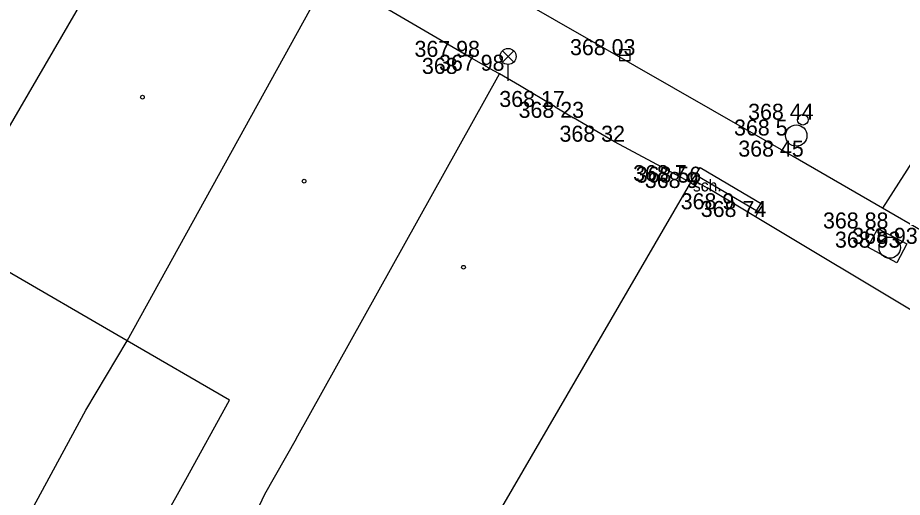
# Model space of a CAD drawing. Extents: x -688316 to -688024, y -973785 to -973591.
# Drawn here: x -688150.19 to -688108.72, y -973719.16 to -973696.66 of the extents above; entities that cross this region are included whole.
import ezdxf

# ---------------------------------------------------------------- set-up
doc = ezdxf.new("R2010")
doc.units = 0
for name, color, linetype in [('Vrstva 10', 7, 'Continuous'), ('Vrstva 11', 7, 'Continuous'), ('Vrstva 27', 7, 'Continuous'), ('Vrstva 28_Verejne osvetleni', 7, 'Continuous'), ('Vrstva 3', 7, 'Continuous'), ('Vrstva 33', 7, 'Continuous'), ('Vrstva 41', 7, 'Continuous'), ('Vrstva 5', 7, 'Continuous'), ('Vrstva 56', 7, 'Continuous'), ('Vrstva 58', 7, 'Continuous'), ('Vrstva 6', 7, 'Continuous'), ('Vrstva 7', 7, 'Continuous')]:
    doc.layers.add(name, color=color, linetype=linetype)

# ---------------------------------------------------------------- blocks, each defined once
blk = doc.blocks.new('B_NESP')
at = {"layer": 'Vrstva 58'}
blk.add_circle((0, 0), 0.875, dxfattribs=at)
blk = doc.blocks.new('SKSCH0')
at = {"layer": 'Vrstva 41'}
blk.add_text('sch.', height=5.5, dxfattribs=at).set_placement((-8.15, -3.04))
blk = doc.blocks.new('VP')
at = {"layer": 'Vrstva 27'}
blk.add_line((-2.5, 0), (2.5, 0), dxfattribs=at)
blk.add_lwpolyline([(-2.5, -2.5), (2.5, -2.5), (2.5, 2.5), (-2.5, 2.5)], close=True, dxfattribs=at)
blk = doc.blocks.new('SAK')
at = {"layer": 'Vrstva 27'}
blk.add_circle((0, 0), 5, dxfattribs=at)
blk = doc.blocks.new('SV')
at = {"layer": 'Vrstva 28_Verejne osvetleni'}
blk.add_circle((0, 0), 2.5, dxfattribs=at)
blk = doc.blocks.new('LAO')
at = {"layer": 'Vrstva 33'}
for p, q in [((-2.65, 14.16), (2.65, 8.85)), ((-2.65, 8.85), (2.65, 14.16)), ((0, 0), (0, 7.75))]:
    blk.add_line(p, q, dxfattribs=at)
blk.add_circle((0, 11.5), 3.75, dxfattribs=at)

msp = doc.modelspace()

# ---------------------------------------------------------------- linework, layer by layer
at = {"layer": 'Vrstva 10'}
for p, q in [((-688113.84, -973703.18), (-688128.61, -973694.7)), ((-688104.76, -973697.92), (-688109.65, -973705.6)), ((-688109.65, -973705.6), (-688113.84, -973703.18)), ((-688098.57, -973712.02), (-688109.65, -973705.6))]:
    msp.add_line(p, q, dxfattribs=at)
msp.add_lwpolyline([(-688109.87, -973706.55), (-688108.5, -973707.27), (-688108.98, -973708.16), (-688110.34, -973707.43), (-688109.87, -973706.55)], dxfattribs=at)
at = {"layer": 'Vrstva 11'}
msp.add_lwpolyline([(-688118.65, -973704.4), (-688118.4, -973704.04), (-688118.19, -973703.69), (-688115.26, -973705.42), (-688115.47, -973705.76), (-688115.6, -973706.01)], dxfattribs=at)
at = {"layer": 'Vrstva 5'}
for p, q in [((-688153.55, -973706.89), (-688143.74, -973689.99)), ((-688145.05, -973711.82), (-688135.58, -973694.66)), ((-688137.14, -973716.41), (-688127.6, -973699.3)), ((-688124.99, -973700.85), (-688124.14, -973701.36)), ((-688118.65, -973704.4), (-688122.21, -973702.48)), ((-688118.65, -973704.4), (-688129.85, -973723.67)), ((-688115.6, -973706.01), (-688116.19, -973705.65)), ((-688101.32, -973714.57), (-688115.6, -973706.01)), ((-688145.05, -973711.82), (-688153.55, -973706.89)), ((-688140.26, -973714.6), (-688145.05, -973711.82)), ((-688142.31, -973718.32), (-688140.26, -973714.6)), ((-688137.14, -973716.41), (-688138.61, -973719.03)), ((-688146.85, -973726.56), (-688142.31, -973718.32)), ((-688138.61, -973719.03), (-688143.36, -973728.87))]:
    msp.add_line(p, q, dxfattribs=at)
for points in [[(-688129.02, -973698.5), (-688135.58, -973694.66), (-688142.07, -973691)], [(-688126.67, -973699.85), (-688127.6, -973699.3), (-688127.87, -973699.15)], [(-688118.65, -973704.4), (-688118.51, -973704.48), (-688118.42, -973704.33), (-688117.87, -973704.65)]]:
    msp.add_lwpolyline(points, dxfattribs=at)
at = {"layer": 'Vrstva 56'}
msp.add_line((-688118.4, -973704.04), (-688115.47, -973705.76), dxfattribs=at)
at = {"layer": 'Vrstva 6'}
for p, q in [((-688127.87, -973699.15), (-688129.02, -973698.5)), ((-688124.99, -973700.85), (-688126.67, -973699.85)), ((-688122.21, -973702.48), (-688124.14, -973701.36)), ((-688116.19, -973705.65), (-688117.87, -973704.65))]:
    msp.add_line(p, q, dxfattribs=at)
at = {"layer": 'Vrstva 7'}
for p, q in [((-688147, -973715.07), (-688145.05, -973711.82)), ((-688151.48, -973723.34), (-688147, -973715.07))]:
    msp.add_line(p, q, dxfattribs=at)

# ---------------------------------------------------------------- block references
at = {"layer": 'Vrstva 27', "xscale": 0.1, "yscale": 0.10000000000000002}
for name, p in [('VP', (-688121.73, -973698.42)), ('SAK', (-688113.69, -973702.19)), ('SAK', (-688109.31, -973707.45))]:
    msp.add_blockref(name, p, dxfattribs=at)
at = {"layer": 'Vrstva 28_Verejne osvetleni', "xscale": 0.1, "yscale": 0.10000000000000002}
msp.add_blockref('SV', (-688113.38, -973701.45), dxfattribs=at)
at = {"layer": 'Vrstva 33', "xscale": 0.1, "yscale": 0.10000000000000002}
msp.add_blockref('LAO', (-688127.2, -973699.63), dxfattribs=at)
at = {"layer": 'Vrstva 41', "xscale": 0.1, "yscale": 0.10000000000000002}
msp.add_blockref('SKSCH0', (-688117.72, -973704.51), dxfattribs=at)
at = {"layer": 'Vrstva 58', "xscale": 0.1, "yscale": 0.10000000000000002}
for p in [(-688144.34, -973700.39), (-688144.34, -973700.39), (-688144.34, -973700.39), (-688144.34, -973700.39), (-688136.76, -973704.33), (-688136.76, -973704.33), (-688136.76, -973704.33), (-688136.76, -973704.33), (-688129.29, -973708.37), (-688129.29, -973708.37), (-688129.29, -973708.37), (-688129.29, -973708.37)]:
    msp.add_blockref('B_NESP', p, dxfattribs=at)

# ---------------------------------------------------------------- texts
at = {"layer": 'Vrstva 3'}
for s, p in [('367 98 ', (-688131.586, -973698.5)), ('367 98 ', (-688131.586, -973698.5)), ('367 98 ', (-688131.586, -973698.5)), ('367 98 ', (-688131.586, -973698.5)), ('367 98 ', (-688131.586, -973698.5)), ('367 98 ', (-688131.586, -973698.5)), ('367 98 ', (-688131.586, -973698.5)), ('368 03 ', (-688124.296, -973698.42)), ('368 03 ', (-688124.296, -973698.42)), ('368 03 ', (-688124.296, -973698.42)), ('368 03 ', (-688124.296, -973698.42)), ('368 03 ', (-688124.296, -973698.42)), ('368 03 ', (-688124.296, -973698.42)), ('368 03 ', (-688124.296, -973698.42)), ('367 98 ', (-688130.436, -973699.15)), ('367 98 ', (-688130.436, -973699.15)), ('367 98 ', (-688130.436, -973699.15)), ('367 98 ', (-688130.436, -973699.15)), ('367 98 ', (-688130.436, -973699.15)), ('367 98 ', (-688130.436, -973699.15)), ('367 98 ', (-688130.436, -973699.15)), ('368    ', (-688131.237, -973699.3)), ('368    ', (-688131.237, -973699.3)), ('368    ', (-688131.237, -973699.3)), ('368    ', (-688131.237, -973699.3)), ('368    ', (-688131.237, -973699.3)), ('368    ', (-688131.237, -973699.3)), ('368    ', (-688131.237, -973699.3)), ('368 17 ', (-688127.611, -973700.85)), ('368 17 ', (-688127.611, -973700.85)), ('368 17 ', (-688127.611, -973700.85)), ('368 17 ', (-688127.611, -973700.85)), ('368 17 ', (-688127.611, -973700.85)), ('368 17 ', (-688127.611, -973700.85)), ('368 17 ', (-688127.611, -973700.85)), ('368 23 ', (-688126.706, -973701.36)), ('368 23 ', (-688126.706, -973701.36)), ('368 23 ', (-688126.706, -973701.36)), ('368 23 ', (-688126.706, -973701.36)), ('368 23 ', (-688126.706, -973701.36)), ('368 23 ', (-688126.706, -973701.36)), ('368 23 ', (-688126.706, -973701.36)), ('368 44 ', (-688115.946, -973701.45)), ('368 44 ', (-688115.946, -973701.45)), ('368 44 ', (-688115.946, -973701.45)), ('368 44 ', (-688115.946, -973701.45)), ('368 44 ', (-688115.946, -973701.45)), ('368 44 ', (-688115.946, -973701.45)), ('368 44 ', (-688115.946, -973701.45)), ('368 5  ', (-688116.607, -973702.19)), ('368 5  ', (-688116.607, -973702.19)), ('368 5  ', (-688116.607, -973702.19)), ('368 5  ', (-688116.607, -973702.19)), ('368 5  ', (-688116.607, -973702.19)), ('368 5  ', (-688116.607, -973702.19)), ('368 5  ', (-688116.607, -973702.19)), ('368 32 ', (-688124.788, -973702.48)), ('368 32 ', (-688124.788, -973702.48)), ('368 32 ', (-688124.788, -973702.48)), ('368 32 ', (-688124.788, -973702.48)), ('368 32 ', (-688124.788, -973702.48)), ('368 32 ', (-688124.788, -973702.48)), ('368 32 ', (-688124.788, -973702.48)), ('368 45 ', (-688116.406, -973703.18)), ('368 45 ', (-688116.406, -973703.18)), ('368 45 ', (-688116.406, -973703.18)), ('368 45 ', (-688116.406, -973703.18)), ('368 45 ', (-688116.406, -973703.18)), ('368 45 ', (-688116.406, -973703.18)), ('368 45 ', (-688116.406, -973703.18)), ('368 7  ', (-688121.337, -973704.33)), ('368 7  ', (-688121.337, -973704.33)), ('368 7  ', (-688121.337, -973704.33)), ('368 7  ', (-688121.337, -973704.33)), ('368 7  ', (-688121.337, -973704.33)), ('368 7  ', (-688121.337, -973704.33)), ('368 7  ', (-688121.337, -973704.33)), ('368 56 ', (-688121.216, -973704.4)), ('368 56 ', (-688121.216, -973704.4)), ('368 56 ', (-688121.216, -973704.4)), ('368 56 ', (-688121.216, -973704.4)), ('368 56 ', (-688121.216, -973704.4)), ('368 56 ', (-688121.216, -973704.4)), ('368 56 ', (-688121.216, -973704.4)), ('368 9  ', (-688120.787, -973704.65)), ('368 9  ', (-688120.787, -973704.65)), ('368 9  ', (-688120.787, -973704.65)), ('368 9  ', (-688120.787, -973704.65)), ('368 9  ', (-688120.787, -973704.65)), ('368 9  ', (-688120.787, -973704.65)), ('368 9  ', (-688120.787, -973704.65)), ('368 9  ', (-688119.107, -973705.65)), ('368 9  ', (-688119.107, -973705.65)), ('368 9  ', (-688119.107, -973705.65)), ('368 9  ', (-688119.107, -973705.65)), ('368 9  ', (-688119.107, -973705.65)), ('368 9  ', (-688119.107, -973705.65)), ('368 9  ', (-688119.107, -973705.65)), ('368 74 ', (-688118.166, -973706.01)), ('368 74 ', (-688118.166, -973706.01)), ('368 74 ', (-688118.166, -973706.01)), ('368 74 ', (-688118.166, -973706.01)), ('368 74 ', (-688118.166, -973706.01)), ('368 74 ', (-688118.166, -973706.01)), ('368 74 ', (-688118.166, -973706.01)), ('368 88 ', (-688112.436, -973706.55)), ('368 88 ', (-688112.436, -973706.55)), ('368 88 ', (-688112.436, -973706.55)), ('368 88 ', (-688112.436, -973706.55)), ('368 88 ', (-688112.436, -973706.55)), ('368 88 ', (-688112.436, -973706.55)), ('368 88 ', (-688112.436, -973706.55)), ('368 93 ', (-688111.876, -973707.45)), ('368 93 ', (-688111.876, -973707.45)), ('368 93 ', (-688111.876, -973707.45)), ('368 93 ', (-688111.876, -973707.45)), ('368 93 ', (-688111.876, -973707.45)), ('368 93 ', (-688111.876, -973707.45)), ('368 93 ', (-688111.876, -973707.45)), ('368 93 ', (-688111.066, -973707.27)), ('368 93 ', (-688111.066, -973707.27)), ('368 93 ', (-688111.066, -973707.27)), ('368 93 ', (-688111.066, -973707.27)), ('368 93 ', (-688111.066, -973707.27)), ('368 93 ', (-688111.066, -973707.27)), ('368 93 ', (-688111.066, -973707.27))]:
    msp.add_text(s, height=0.75, dxfattribs=at).set_placement(p)

doc.saveas('drawing.dxf')
